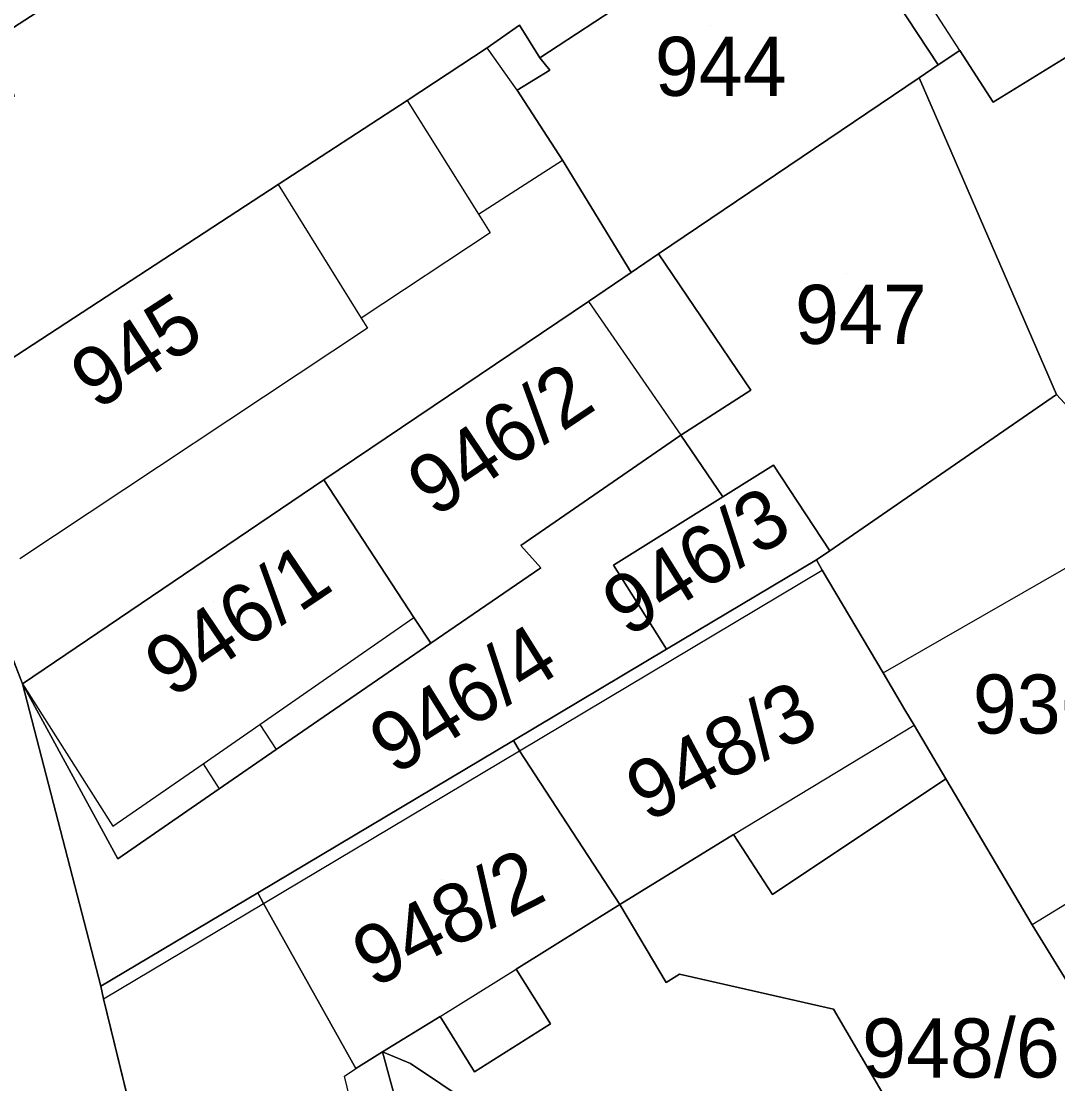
# Model space of a CAD drawing. Extents: x -263943 to -261149, y -1236934 to -1230686.
# Drawn here: x -262695.05 to -262659.95, y -1235327.15 to -1235291.16 of the extents above; entities that cross this region are included whole.
import ezdxf

# ---------------------------------------------------------------- set-up
doc = ezdxf.new("R2010")
doc.units = 0
for name, color, linetype in [('body_kn', 7, 'Continuous'), ('kladpar_druhypozemkov', 7, 'Continuous'), ('kladpar_hranice', 7, 'Continuous'), ('kladpar_parcelnecisla', 7, 'Continuous'), ('kladpar_plochy', 7, 'Continuous'), ('zappar_hrandruhpozemk', 7, 'Continuous')]:
    doc.layers.add(name, color=color, linetype=linetype)

msp = doc.modelspace()

# ---------------------------------------------------------------- linework, layer by layer
at = {"layer": 'body_kn'}
for p, q in [((-262678.18, -1235291.3), (-262678.18, -1235291.3)), ((-262679.28, -1235292.06), (-262679.28, -1235292.06)), ((-262663.27, -1235292.15), (-262663.27, -1235292.15)), ((-262663.27, -1235292.15), (-262663.27, -1235292.15)), ((-262677.49, -1235292.4), (-262677.49, -1235292.4)), ((-262664, -1235292.64), (-262664, -1235292.64)), ((-262677.15, -1235292.82), (-262677.15, -1235292.82)), ((-262677.15, -1235292.82), (-262677.15, -1235292.82)), ((-262664.65, -1235293.08), (-262664.65, -1235293.08)), ((-262678.26, -1235293.5), (-262678.26, -1235293.5)), ((-262678.26, -1235293.5), (-262678.26, -1235293.5)), ((-262681.99, -1235293.85), (-262681.99, -1235293.85)), ((-262681.99, -1235293.85), (-262681.99, -1235293.85)), ((-262662.14, -1235293.9), (-262662.14, -1235293.9)), ((-262676.73, -1235295.87), (-262676.73, -1235295.87)), ((-262686.36, -1235296.69), (-262686.36, -1235296.69)), ((-262686.36, -1235296.69), (-262686.36, -1235296.69)), ((-262679.57, -1235297.7), (-262679.57, -1235297.7)), ((-262679.18, -1235298.33), (-262679.18, -1235298.33)), ((-262673.47, -1235299.04), (-262673.47, -1235299.04)), ((-262673.47, -1235299.04), (-262673.47, -1235299.04)), ((-262674.4, -1235299.67), (-262674.4, -1235299.67)), ((-262675.85, -1235300.65), (-262675.85, -1235300.65)), ((-262675.85, -1235300.65), (-262675.85, -1235300.65)), ((-262683.54, -1235301.22), (-262683.54, -1235301.22)), ((-262683.54, -1235301.22), (-262683.54, -1235301.22)), ((-262683.33, -1235301.56), (-262683.33, -1235301.56)), ((-262670.35, -1235303.66), (-262670.35, -1235303.66)), ((-262670.35, -1235303.66), (-262670.35, -1235303.66)), ((-262660, -1235303.81), (-262660, -1235303.81)), ((-262672.72, -1235305.18), (-262672.72, -1235305.18)), ((-262669.58, -1235306.2), (-262669.58, -1235306.2)), ((-262669.58, -1235306.2), (-262669.58, -1235306.2)), ((-262684.81, -1235306.7), (-262684.81, -1235306.7)), ((-262671.3, -1235307.27), (-262671.3, -1235307.27)), ((-262671.3, -1235307.27), (-262671.3, -1235307.27)), ((-262678.14, -1235308.92), (-262678.14, -1235308.92)), ((-262667.67, -1235309.1), (-262667.67, -1235309.1)), ((-262675, -1235309.59), (-262675, -1235309.59)), ((-262668.13, -1235309.41), (-262668.13, -1235309.41)), ((-262668.13, -1235309.41), (-262668.13, -1235309.41)), ((-262677.46, -1235309.68), (-262677.46, -1235309.68)), ((-262667.93, -1235309.76), (-262667.93, -1235309.76)), ((-262681.76, -1235311.36), (-262681.76, -1235311.36)), ((-262681.19, -1235312.23), (-262681.19, -1235312.23)), ((-262673.2, -1235312.43), (-262673.2, -1235312.43)), ((-262665.87, -1235313.23), (-262665.87, -1235313.23)), ((-262665.87, -1235313.23), (-262665.87, -1235313.23)), ((-262695.01, -1235313.6), (-262695.01, -1235313.6)), ((-262695.01, -1235313.6), (-262695.01, -1235313.6)), ((-262665.13, -1235314.49), (-262665.13, -1235314.49)), ((-262686.98, -1235314.98), (-262686.98, -1235314.98)), ((-262686.98, -1235314.98), (-262686.98, -1235314.98)), ((-262664.82, -1235315.01), (-262664.82, -1235315.01)), ((-262678.38, -1235315.52), (-262678.38, -1235315.52)), ((-262678.38, -1235315.52), (-262678.38, -1235315.52)), ((-262686.42, -1235315.83), (-262686.42, -1235315.83)), ((-262686.42, -1235315.83), (-262686.42, -1235315.83)), ((-262678.18, -1235315.87), (-262678.18, -1235315.87)), ((-262678.18, -1235315.87), (-262678.18, -1235315.87)), ((-262688.89, -1235316.31), (-262688.89, -1235316.31)), ((-262688.89, -1235316.31), (-262688.89, -1235316.31)), ((-262663.75, -1235316.82), (-262663.75, -1235316.82)), ((-262688.35, -1235317.16), (-262688.35, -1235317.16)), ((-262691.95, -1235318.43), (-262691.95, -1235318.43)), ((-262670.93, -1235318.71), (-262670.93, -1235318.71)), ((-262670.93, -1235318.71), (-262670.93, -1235318.71)), ((-262691.78, -1235319.53), (-262691.78, -1235319.53)), ((-262687.04, -1235320.68), (-262687.04, -1235320.68)), ((-262669.61, -1235320.74), (-262669.61, -1235320.74)), ((-262686.85, -1235321.04), (-262686.85, -1235321.04)), ((-262686.85, -1235321.04), (-262686.85, -1235321.04)), ((-262674.78, -1235321.08), (-262674.78, -1235321.08)), ((-262660.82, -1235321.77), (-262660.82, -1235321.77)), ((-262660.82, -1235321.77), (-262660.82, -1235321.77)), ((-262678.29, -1235323.27), (-262678.29, -1235323.27)), ((-262672.76, -1235323.44), (-262672.76, -1235323.44)), ((-262692.36, -1235323.85), (-262692.36, -1235323.85)), ((-262692.36, -1235323.85), (-262692.36, -1235323.85)), ((-262673.21, -1235323.72), (-262673.21, -1235323.72)), ((-262692.27, -1235324.27), (-262692.27, -1235324.27)), ((-262692.27, -1235324.27), (-262692.27, -1235324.27)), ((-262667.55, -1235324.62), (-262667.55, -1235324.62)), ((-262667.55, -1235324.62), (-262667.55, -1235324.62)), ((-262680.87, -1235324.87), (-262680.87, -1235324.87)), ((-262680.87, -1235324.87), (-262680.87, -1235324.87)), ((-262677.13, -1235325.12), (-262677.13, -1235325.12)), ((-262682.82, -1235326.07), (-262682.82, -1235326.07)), ((-262681.87, -1235326.46), (-262681.87, -1235326.46)), ((-262684.11, -1235326.89), (-262684.11, -1235326.89)), ((-262683.72, -1235326.64), (-262683.72, -1235326.64)), ((-262679.71, -1235326.75), (-262679.71, -1235326.75))]:
    msp.add_line(p, q, dxfattribs=at)
at = {"layer": 'kladpar_druhypozemkov'}
for p, q in [((-262671.7, -1235291.29), (-262671.7, -1235291.29)), ((-262667.1, -1235299.69), (-262667.1, -1235299.69)), ((-262691.4, -1235301.29), (-262691.4, -1235301.29)), ((-262678.73, -1235304), (-262678.73, -1235304)), ((-262671.3, -1235308.09), (-262671.3, -1235308.09)), ((-262688.56, -1235310.83), (-262688.56, -1235310.83)), ((-262680.31, -1235313.26), (-262680.31, -1235313.26)), ((-262670.68, -1235314.02), (-262670.68, -1235314.02)), ((-262680.82, -1235320.23), (-262680.82, -1235320.23)), ((-262662.51, -1235325.11), (-262662.51, -1235325.11))]:
    msp.add_line(p, q, dxfattribs=at)
at = {"layer": 'kladpar_hranice'}
for points in [[(-262676.27, -1235264.78), (-262679.48, -1235274.02), (-262684.99, -1235272.08), (-262688.7, -1235287.08), (-262695.9, -1235291.75), (-262695.3, -1235293.7), (-262700.81, -1235297.35), (-262701.83, -1235294.04), (-262703.36, -1235291.16), (-262707.45, -1235283.04), (-262707.87, -1235282.36), (-262707.2, -1235281.6), (-262693.73, -1235269.89), (-262692.97, -1235269.21), (-262686.79, -1235261.58), (-262676.27, -1235264.78)], [(-262657.93, -1235288.6), (-262656.72, -1235290.51), (-262657.4, -1235290.93), (-262657.74, -1235291.19), (-262662.14, -1235293.9), (-262663.27, -1235292.15), (-262664, -1235292.64), (-262668.18, -1235286.29), (-262667.96, -1235286.14), (-262671.07, -1235281.21), (-262670.56, -1235280.87), (-262665.73, -1235277.99), (-262663.85, -1235280.92), (-262661.9, -1235283.94), (-262661.14, -1235283.57), (-262659.08, -1235286.79), (-262657.93, -1235288.6)], [(-262668.18, -1235286.29), (-262677.49, -1235292.4), (-262678.18, -1235291.3), (-262679.28, -1235292.06), (-262681.99, -1235293.85), (-262686.36, -1235296.69), (-262698.27, -1235304.47), (-262698.51, -1235304.63), (-262700.81, -1235297.35), (-262695.3, -1235293.7), (-262695.9, -1235291.75), (-262688.7, -1235287.08)], [(-262673.47, -1235299.04), (-262674.4, -1235299.67), (-262676.73, -1235295.87), (-262678.26, -1235293.5), (-262677.15, -1235292.82), (-262677.49, -1235292.4), (-262668.18, -1235286.29), (-262664, -1235292.64), (-262664.65, -1235293.08), (-262673.47, -1235299.04)], [(-262703.36, -1235291.16), (-262701.83, -1235294.04), (-262700.81, -1235297.35), (-262698.51, -1235304.63), (-262695.01, -1235313.6), (-262692.36, -1235323.85), (-262692.27, -1235324.27), (-262689.96, -1235333.76), (-262689.18, -1235341.72), (-262688.83, -1235346.04), (-262687.45, -1235357.04), (-262687.28, -1235357.72), (-262687.7, -1235357.81), (-262687.96, -1235358.49), (-262688.55, -1235358.74), (-262688.12, -1235360.43), (-262687.53, -1235360.52), (-262687.19, -1235361.11), (-262686.51, -1235361.02), (-262685.65, -1235363.9), (-262685.14, -1235365.68), (-262686.58, -1235366.11), (-262685.81, -1235369.24)], [(-262646.95, -1235300.15), (-262644.74, -1235301.84), (-262643.99, -1235302.54), (-262647.2, -1235304.81), (-262648.73, -1235302.78), (-262656.94, -1235307.11), (-262660, -1235303.81), (-262664.65, -1235293.08), (-262664, -1235292.64), (-262663.27, -1235292.15), (-262662.14, -1235293.9), (-262657.74, -1235291.19), (-262657.82, -1235294.24), (-262655.19, -1235295.08), (-262652.64, -1235296.26), (-262649.75, -1235298.04), (-262646.95, -1235300.15)], [(-262677.15, -1235292.82), (-262678.26, -1235293.5), (-262676.73, -1235295.87), (-262674.4, -1235299.67), (-262675.85, -1235300.65), (-262684.81, -1235306.7), (-262695.01, -1235313.6), (-262698.51, -1235304.63), (-262698.27, -1235304.47), (-262686.36, -1235296.69), (-262681.99, -1235293.85), (-262679.28, -1235292.06), (-262678.18, -1235291.3), (-262677.49, -1235292.4), (-262677.15, -1235292.82)], [(-262669.58, -1235306.2), (-262671.3, -1235307.27), (-262672.72, -1235305.18), (-262670.35, -1235303.66), (-262673.47, -1235299.04), (-262664.65, -1235293.08), (-262660, -1235303.81), (-262667.67, -1235309.1), (-262669.58, -1235306.2)], [(-262670.35, -1235303.66), (-262672.72, -1235305.18), (-262678.14, -1235308.92), (-262677.46, -1235309.68), (-262681.19, -1235312.23), (-262681.76, -1235311.36), (-262684.81, -1235306.7), (-262675.85, -1235300.65), (-262674.4, -1235299.67), (-262673.47, -1235299.04), (-262670.35, -1235303.66)], [(-262660.82, -1235321.77), (-262663.75, -1235316.82), (-262664.82, -1235315.01), (-262665.13, -1235314.49), (-262665.87, -1235313.23), (-262667.93, -1235309.76), (-262668.13, -1235309.41), (-262667.67, -1235309.1), (-262660, -1235303.81), (-262656.94, -1235307.11), (-262649.8, -1235318.28), (-262648.35, -1235320.39), (-262657.75, -1235326.76), (-262660.82, -1235321.77)], [(-262671.3, -1235307.27), (-262675, -1235309.59), (-262673.2, -1235312.43), (-262678.38, -1235315.52), (-262687.04, -1235320.68), (-262692.36, -1235323.85), (-262695.01, -1235313.6), (-262691.78, -1235319.53), (-262688.35, -1235317.16), (-262686.42, -1235315.83), (-262681.19, -1235312.23), (-262677.46, -1235309.68), (-262678.14, -1235308.92), (-262672.72, -1235305.18), (-262671.3, -1235307.27)], [(-262668.13, -1235309.41), (-262673.2, -1235312.43), (-262675, -1235309.59), (-262671.3, -1235307.27), (-262669.58, -1235306.2), (-262667.67, -1235309.1), (-262668.13, -1235309.41)], [(-262686.42, -1235315.83), (-262688.35, -1235317.16), (-262691.78, -1235319.53), (-262695.01, -1235313.6), (-262684.81, -1235306.7), (-262681.76, -1235311.36), (-262681.19, -1235312.23), (-262686.42, -1235315.83)], [(-262665.87, -1235313.23), (-262665.13, -1235314.49), (-262664.82, -1235315.01), (-262663.75, -1235316.82), (-262669.61, -1235320.74), (-262670.93, -1235318.71), (-262674.78, -1235321.08), (-262678.18, -1235315.87), (-262678.38, -1235315.52), (-262673.2, -1235312.43), (-262668.13, -1235309.41), (-262667.93, -1235309.76), (-262665.87, -1235313.23)], [(-262678.38, -1235315.52), (-262678.18, -1235315.87), (-262674.78, -1235321.08), (-262678.29, -1235323.27), (-262677.13, -1235325.12), (-262679.71, -1235326.75), (-262680.87, -1235324.87), (-262682.82, -1235326.07), (-262683.72, -1235326.64), (-262686.85, -1235321.04), (-262687.04, -1235320.68), (-262678.38, -1235315.52)], [(-262660.82, -1235321.77), (-262657.75, -1235326.76), (-262658.85, -1235327.53), (-262658.6, -1235327.95), (-262663.96, -1235330.77), (-262667.55, -1235324.62), (-262672.76, -1235323.44), (-262673.21, -1235323.72), (-262674.78, -1235321.08), (-262670.93, -1235318.71), (-262669.61, -1235320.74), (-262663.75, -1235316.82), (-262660.82, -1235321.77)], [(-262692.36, -1235323.85), (-262687.04, -1235320.68), (-262686.85, -1235321.04), (-262683.72, -1235326.64), (-262682.82, -1235326.07), (-262681.33, -1235331.56), (-262682.87, -1235331.92), (-262689.96, -1235333.76), (-262692.27, -1235324.27), (-262692.36, -1235323.85)], [(-262667.55, -1235324.62), (-262663.96, -1235330.77), (-262674.12, -1235335.81), (-262677.76, -1235329.22), (-262681.87, -1235326.46), (-262682.82, -1235326.07), (-262680.87, -1235324.87), (-262679.71, -1235326.75), (-262677.13, -1235325.12), (-262678.29, -1235323.27), (-262674.78, -1235321.08), (-262673.21, -1235323.72), (-262672.76, -1235323.44), (-262667.55, -1235324.62)], [(-262689.96, -1235333.76), (-262682.87, -1235331.92), (-262681.33, -1235331.56), (-262682.82, -1235326.07), (-262681.87, -1235326.46), (-262677.76, -1235329.22), (-262674.12, -1235335.81), (-262684.26, -1235340.48), (-262686.92, -1235341.22), (-262689.18, -1235341.72), (-262689.96, -1235333.76)]]:
    msp.add_lwpolyline(points, dxfattribs=at)
at = {"layer": 'kladpar_plochy'}
for p, q in [((-262698.51, -1235304.63), (-262695.01, -1235313.6)), ((-262695.01, -1235313.6), (-262692.36, -1235323.85)), ((-262692.36, -1235323.85), (-262692.27, -1235324.27)), ((-262692.27, -1235324.27), (-262689.96, -1235333.76))]:
    msp.add_line(p, q, dxfattribs=at)
for points in [[(-262686.62, -1235261.24), (-262672.28, -1235265.2), (-262673.12, -1235271.3), (-262673.11, -1235274.78), (-262672.35, -1235278.33), (-262670.56, -1235280.87), (-262671.07, -1235281.21), (-262667.96, -1235286.14), (-262668.18, -1235286.29), (-262677.49, -1235292.4), (-262678.18, -1235291.3), (-262679.28, -1235292.06), (-262681.99, -1235293.85), (-262686.36, -1235296.69), (-262698.27, -1235304.47), (-262698.51, -1235304.63), (-262700.81, -1235297.35), (-262695.3, -1235293.7), (-262695.9, -1235291.75), (-262688.7, -1235287.08), (-262684.99, -1235272.08), (-262679.48, -1235274.02), (-262676.27, -1235264.78), (-262686.79, -1235261.58)], [(-262676.27, -1235264.78), (-262679.48, -1235274.02), (-262684.99, -1235272.08), (-262688.7, -1235287.08), (-262695.9, -1235291.75), (-262695.3, -1235293.7), (-262700.81, -1235297.35), (-262701.83, -1235294.04), (-262703.36, -1235291.16), (-262707.45, -1235283.04), (-262707.87, -1235282.36), (-262707.2, -1235281.6), (-262693.73, -1235269.89), (-262692.97, -1235269.21), (-262686.79, -1235261.58)], [(-262657.93, -1235288.6), (-262656.72, -1235290.51), (-262657.4, -1235290.93), (-262657.74, -1235291.19), (-262662.14, -1235293.9), (-262663.27, -1235292.15), (-262664, -1235292.64), (-262668.18, -1235286.29), (-262667.96, -1235286.14), (-262671.07, -1235281.21), (-262670.56, -1235280.87), (-262665.73, -1235277.99), (-262663.85, -1235280.92), (-262661.9, -1235283.94), (-262661.14, -1235283.57), (-262659.08, -1235286.79)], [(-262673.47, -1235299.04), (-262674.4, -1235299.67), (-262676.73, -1235295.87), (-262678.26, -1235293.5), (-262677.15, -1235292.82), (-262677.49, -1235292.4), (-262668.18, -1235286.29), (-262664, -1235292.64), (-262664.65, -1235293.08)], [(-262646.95, -1235300.15), (-262644.74, -1235301.84), (-262643.99, -1235302.54), (-262647.2, -1235304.81), (-262648.73, -1235302.78), (-262656.94, -1235307.11), (-262660, -1235303.81), (-262664.65, -1235293.08), (-262664, -1235292.64), (-262663.27, -1235292.15), (-262662.14, -1235293.9), (-262657.74, -1235291.19), (-262657.82, -1235294.24), (-262655.19, -1235295.08), (-262652.64, -1235296.26), (-262649.75, -1235298.04)], [(-262677.15, -1235292.82), (-262678.26, -1235293.5), (-262676.73, -1235295.87), (-262674.4, -1235299.67), (-262675.85, -1235300.65), (-262684.81, -1235306.7), (-262695.01, -1235313.6), (-262698.51, -1235304.63), (-262698.27, -1235304.47), (-262686.36, -1235296.69), (-262681.99, -1235293.85), (-262679.28, -1235292.06), (-262678.18, -1235291.3), (-262677.49, -1235292.4)], [(-262669.58, -1235306.2), (-262671.3, -1235307.27), (-262672.72, -1235305.18), (-262670.35, -1235303.66), (-262673.47, -1235299.04), (-262664.65, -1235293.08), (-262660, -1235303.81), (-262667.67, -1235309.1)], [(-262670.35, -1235303.66), (-262672.72, -1235305.18), (-262678.14, -1235308.92), (-262677.46, -1235309.68), (-262681.19, -1235312.23), (-262681.76, -1235311.36), (-262684.81, -1235306.7), (-262675.85, -1235300.65), (-262674.4, -1235299.67), (-262673.47, -1235299.04)], [(-262660.82, -1235321.77), (-262663.75, -1235316.82), (-262664.82, -1235315.01), (-262665.13, -1235314.49), (-262665.87, -1235313.23), (-262667.93, -1235309.76), (-262668.13, -1235309.41), (-262667.67, -1235309.1), (-262660, -1235303.81), (-262656.94, -1235307.11), (-262649.8, -1235318.28), (-262648.35, -1235320.39), (-262657.75, -1235326.76)], [(-262671.3, -1235307.27), (-262675, -1235309.59), (-262673.2, -1235312.43), (-262678.38, -1235315.52), (-262687.04, -1235320.68), (-262692.36, -1235323.85), (-262695.01, -1235313.6), (-262691.78, -1235319.53), (-262688.35, -1235317.16), (-262686.42, -1235315.83), (-262681.19, -1235312.23), (-262677.46, -1235309.68), (-262678.14, -1235308.92), (-262672.72, -1235305.18)], [(-262668.13, -1235309.41), (-262673.2, -1235312.43), (-262675, -1235309.59), (-262671.3, -1235307.27), (-262669.58, -1235306.2), (-262667.67, -1235309.1)], [(-262686.42, -1235315.83), (-262688.35, -1235317.16), (-262691.78, -1235319.53), (-262695.01, -1235313.6), (-262684.81, -1235306.7), (-262681.76, -1235311.36), (-262681.19, -1235312.23)], [(-262665.87, -1235313.23), (-262665.13, -1235314.49), (-262664.82, -1235315.01), (-262663.75, -1235316.82), (-262669.61, -1235320.74), (-262670.93, -1235318.71), (-262674.78, -1235321.08), (-262678.18, -1235315.87), (-262678.38, -1235315.52), (-262673.2, -1235312.43), (-262668.13, -1235309.41), (-262667.93, -1235309.76)], [(-262678.38, -1235315.52), (-262678.18, -1235315.87), (-262674.78, -1235321.08), (-262678.29, -1235323.27), (-262677.13, -1235325.12), (-262679.71, -1235326.75), (-262680.87, -1235324.87), (-262682.82, -1235326.07), (-262683.72, -1235326.64), (-262686.85, -1235321.04), (-262687.04, -1235320.68)], [(-262660.82, -1235321.77), (-262657.75, -1235326.76), (-262658.85, -1235327.53), (-262658.6, -1235327.95), (-262663.96, -1235330.77), (-262667.55, -1235324.62), (-262672.76, -1235323.44), (-262673.21, -1235323.72), (-262674.78, -1235321.08), (-262670.93, -1235318.71), (-262669.61, -1235320.74), (-262663.75, -1235316.82)], [(-262692.36, -1235323.85), (-262687.04, -1235320.68), (-262686.85, -1235321.04), (-262683.72, -1235326.64), (-262682.82, -1235326.07), (-262681.33, -1235331.56), (-262682.87, -1235331.92), (-262689.96, -1235333.76), (-262692.27, -1235324.27)], [(-262667.55, -1235324.62), (-262663.96, -1235330.77), (-262674.12, -1235335.81), (-262677.76, -1235329.22), (-262681.87, -1235326.46), (-262682.82, -1235326.07), (-262680.87, -1235324.87), (-262679.71, -1235326.75), (-262677.13, -1235325.12), (-262678.29, -1235323.27), (-262674.78, -1235321.08), (-262673.21, -1235323.72), (-262672.76, -1235323.44)], [(-262689.96, -1235333.76), (-262682.87, -1235331.92), (-262681.33, -1235331.56), (-262682.82, -1235326.07), (-262681.87, -1235326.46), (-262677.76, -1235329.22), (-262674.12, -1235335.81), (-262684.26, -1235340.48), (-262686.92, -1235341.22), (-262689.18, -1235341.72)]]:
    msp.add_lwpolyline(points, close=True, dxfattribs=at)
at = {"layer": 'zappar_hrandruhpozemk'}
for p, q in [((-262663.27, -1235292.15), (-262668.71, -1235283.74)), ((-262678.26, -1235293.5), (-262679.28, -1235292.06)), ((-262681.99, -1235293.85), (-262679.57, -1235297.7)), ((-262679.57, -1235297.7), (-262676.73, -1235295.87)), ((-262686.36, -1235296.69), (-262683.54, -1235301.22)), ((-262675.85, -1235300.65), (-262672.72, -1235305.18)), ((-262683.54, -1235301.22), (-262683.33, -1235301.56)), ((-262683.33, -1235301.56), (-262695.1, -1235309.37)), ((-262665.87, -1235313.23), (-262657.11, -1235308.21)), ((-262678.18, -1235315.87), (-262667.93, -1235309.76)), ((-262695.01, -1235313.6), (-262691.95, -1235318.43)), ((-262686.98, -1235314.98), (-262686.42, -1235315.83)), ((-262670.93, -1235318.71), (-262664.82, -1235315.01)), ((-262686.85, -1235321.04), (-262678.18, -1235315.87)), ((-262688.89, -1235316.31), (-262688.35, -1235317.16)), ((-262692.27, -1235324.27), (-262686.85, -1235321.04)), ((-262680.87, -1235324.87), (-262678.29, -1235323.27)), ((-262684.11, -1235326.89), (-262683.72, -1235326.64)), ((-262682.87, -1235331.92), (-262684.11, -1235326.89))]:
    msp.add_line(p, q, dxfattribs=at)
for points in [[(-262679.57, -1235297.7), (-262679.18, -1235298.33), (-262683.54, -1235301.22)], [(-262657.11, -1235308.21), (-262652.35, -1235316.59), (-262660.82, -1235321.77)], [(-262691.95, -1235318.43), (-262688.89, -1235316.31), (-262686.98, -1235314.98), (-262681.76, -1235311.36)]]:
    msp.add_lwpolyline(points, dxfattribs=at)

# ---------------------------------------------------------------- texts
at = {"layer": 'kladpar_parcelnecisla'}
for s, p in [('944', (-262673.599, -1235293.69)), ('947', (-262668.852, -1235302.09)), ('936/1', (-262662.832, -1235315.29)), ('948/6', (-262666.58, -1235326.94))]:
    msp.add_text(s, height=2, dxfattribs=at).set_placement(p)
for s, rotation, p in [('945', 33, (-262692.5, -1235304.371)), ('946/2', 34, (-262681.061, -1235308.006)), ('946/3', 32, (-262674.522, -1235312.063)), ('946/1', 34, (-262689.96, -1235314.129)), ('946/4', 32, (-262682.415, -1235316.728)), ('948/3', 28, (-262673.845, -1235318.322)), ('948/2', 27, (-262683.14, -1235323.928))]:
    msp.add_text(s, height=2, rotation=rotation, dxfattribs=at).set_placement(p)

doc.saveas('drawing.dxf')
